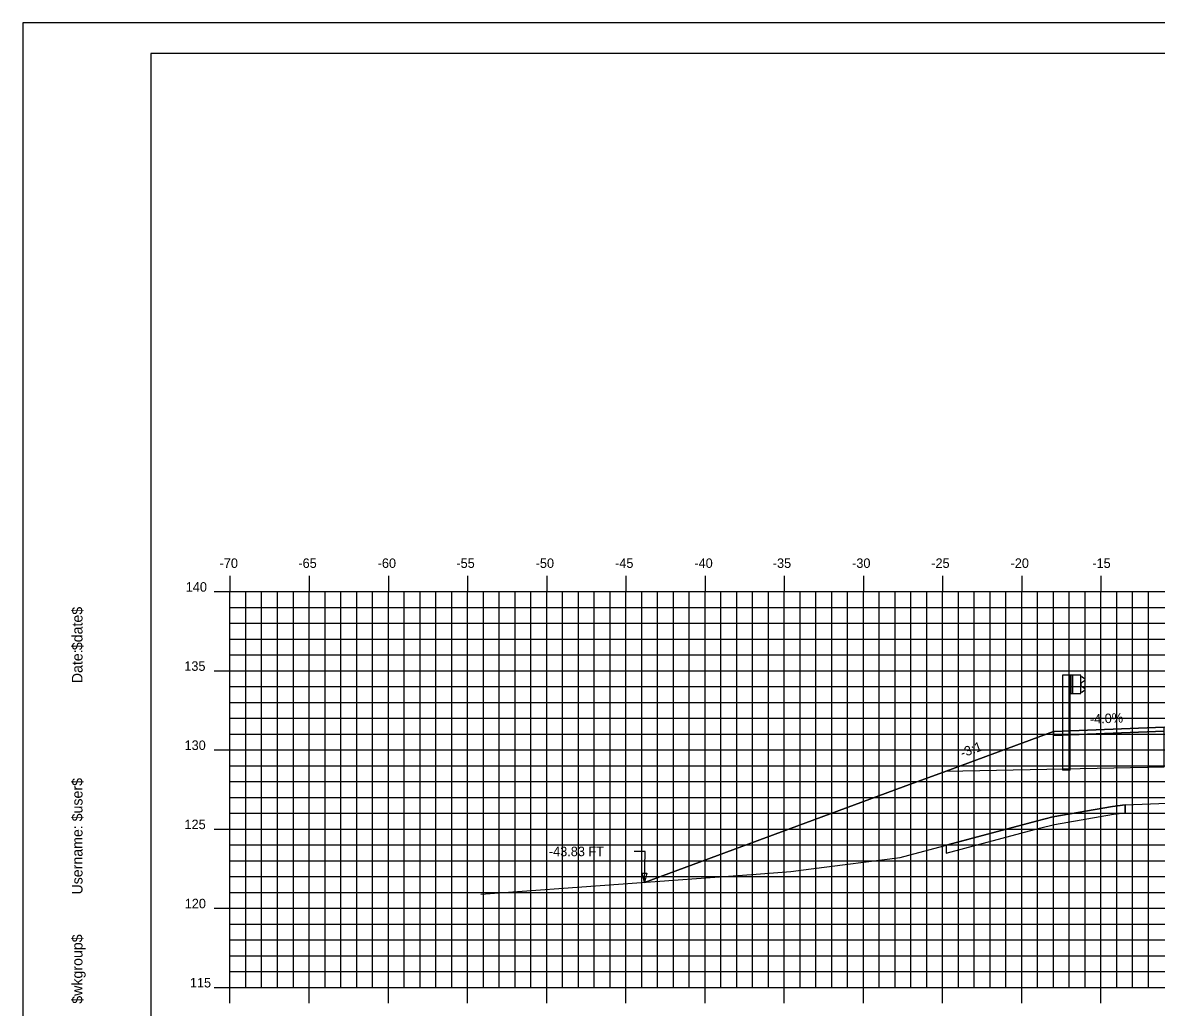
# Model space of a CAD drawing. Extents: x 1146081 to 1146251, y 608981 to 609091.
# Drawn here: x 1146081.1 to 1146152.7, y 609029.1 to 609091.3 of the extents above; entities that cross this region are included whole.
import ezdxf

# ---------------------------------------------------------------- set-up
doc = ezdxf.new("R2010")
doc.units = 0
for name, color, linetype in [('ANNOTATION', 7, 'Continuous'), ('BORDER', 7, 'Continuous'), ('D_Guardrail_Beam_Lt', 7, 'Continuous'), ('D_Roadway_Edge_Shoulder', 7, 'Continuous'), ('D_Roadway_SlopeLines', 7, 'Continuous'), ('D_Roadway_SubGrade', 7, 'Continuous'), ('D_Text_Standard', 7, 'Continuous'), ('H_V ANNOTATION', 7, 'Continuous'), ('MAJOR', 7, 'Continuous'), ('MINOR', 7, 'Continuous'), ('PLOT BOUNDARY', 7, 'Continuous'), ('S_Roadway_Centerline', 7, 'Continuous'), ('SHADING', 7, 'Continuous')]:
    doc.layers.add(name, color=color, linetype=linetype)

msp = doc.modelspace()

# ---------------------------------------------------------------- linework, layer by layer
msp.add_lwpolyline([(1146120.332, 609036.972), (1146136.678, 609043), (1146139.39, 609044), (1146146.157, 609046.495), (1146146.158, 609046.495), (1146153.158, 609046.775), (1146164.158, 609046.995), (1146175.158, 609046.775), (1146185.834, 609046.348), (1146193.131, 609043.915), (1146196.131, 609042.915), (1146201.256, 609041.207)])
at = {"layer": 'BORDER'}
msp.add_lwpolyline([(1146089.158, 608984.335), (1146249.158, 608984.335), (1146249.158, 609089.335), (1146089.158, 609089.335)], close=True, dxfattribs=at)
at = {"layer": 'D_Guardrail_Beam_Lt'}
for p, q in [((1146146.728, 609050.059), (1146146.728, 609044.059)), ((1146147.199, 609050.059), (1146146.728, 609050.059)), ((1146147.887, 609050.059), (1146147.199, 609050.059)), ((1146147.199, 609050.059), (1146147.199, 609048.892)), ((1146147.262, 609050.059), (1146147.262, 609048.892)), ((1146147.366, 609050.059), (1146147.366, 609048.892)), ((1146147.887, 609048.892), (1146147.887, 609050.059)), ((1146147.887, 609049.976), (1146147.961, 609049.961)), ((1146147.891, 609049.511), (1146147.891, 609049.44)), ((1146148.12, 609049.711), (1146147.925, 609049.575)), ((1146147.925, 609049.376), (1146148.12, 609049.24)), ((1146147.977, 609049.954), (1146148.12, 609049.854)), ((1146147.199, 609048.892), (1146147.887, 609048.892)), ((1146147.22, 609044.059), (1146147.22, 609048.892)), ((1146147.961, 609048.99), (1146147.887, 609048.976)), ((1146148.12, 609049.097), (1146147.977, 609048.997)), ((1146147.22, 609044.059), (1146146.728, 609044.059))]:
    msp.add_line(p, q, dxfattribs=at)
for centre, major_axis, start_param, end_param in [((1146147.97, 609049.511), (-0.0789, 0), 5.323254, 6.283185), ((1146147.97, 609049.44), (-0.0789, 0), 6.283185, 7.243116), ((1146147.953, 609049.92), (0.0417, 0), 0.959931, 1.376053), ((1146148.07, 609049.783), (0.0877, 0), 5.323254, 7.243116), ((1146147.953, 609049.031), (0.0417, 0), 4.907132, 5.323254), ((1146148.07, 609049.168), (0.0877, 0), 5.323254, 7.243116)]:
    msp.add_ellipse(centre, major_axis=major_axis, ratio=0.995501, start_param=start_param, end_param=end_param, dxfattribs=at)
at = {"layer": 'D_Roadway_Edge_Shoulder'}
msp.add_lwpolyline([(1146153.158, 609046.775), (1146146.158, 609046.495), (1146146.158, 609046.245), (1146153.158, 609046.525)], close=True, dxfattribs=at)
at = {"layer": 'D_Roadway_SlopeLines'}
for points in [[(1146139.39, 609044), (1146136.678, 609043)], [(1146136.678, 609043), (1146120.332, 609036.972)]]:
    msp.add_lwpolyline(points, dxfattribs=at)
at = {"layer": 'D_Roadway_SubGrade'}
for p, q in [((1146150.681, 609041.862), (1146150.681, 609041.362)), ((1146139.39, 609039.329), (1146139.39, 609038.812))]:
    msp.add_line(p, q, dxfattribs=at)
msp.add_lwpolyline([(1146153.158, 609046.358), (1146153.158, 609046.525), (1146146.158, 609046.245), (1146146.158, 609046.495), (1146146.157, 609046.495), (1146139.39, 609044), (1146153.158, 609044.275)], close=True, dxfattribs=at)
msp.add_lwpolyline([(1146139.39, 609038.812), (1146145.288, 609040.387), (1146146.223, 609040.633), (1146149.952, 609041.275), (1146150.681, 609041.359)], dxfattribs=at)
at = {"layer": 'D_Text_Standard'}
msp.add_lwpolyline([(1146120.332, 609036.972), (1146120.367, 609038.927), (1146119.687, 609038.927)], dxfattribs=at)
msp.add_lwpolyline([(1146120.332, 609036.972), (1146120.197, 609037.557), (1146120.488, 609037.552)], close=True, dxfattribs=at)
at = {"layer": 'MAJOR'}
for p, q in [((1146094.158, 609056.337), (1146094.158, 609055.335)), ((1146099.158, 609056.337), (1146099.158, 609055.335)), ((1146104.158, 609056.337), (1146104.158, 609055.335)), ((1146109.158, 609056.337), (1146109.158, 609055.335)), ((1146114.158, 609056.337), (1146114.158, 609055.335)), ((1146119.158, 609056.337), (1146119.158, 609055.335)), ((1146124.158, 609056.337), (1146124.158, 609055.335)), ((1146129.158, 609056.337), (1146129.158, 609055.335)), ((1146134.158, 609056.337), (1146134.158, 609055.335)), ((1146139.158, 609056.337), (1146139.158, 609055.335)), ((1146144.158, 609056.337), (1146144.158, 609055.335)), ((1146149.158, 609056.337), (1146149.158, 609055.335)), ((1146093.156, 609055.335), (1146094.158, 609055.335)), ((1146094.158, 609055.335), (1146234.158, 609055.335)), ((1146094.158, 609030.335), (1146094.158, 609055.335)), ((1146094.158, 609030.335), (1146094.158, 609055.335)), ((1146094.158, 609055.335), (1146234.158, 609055.335)), ((1146099.158, 609030.335), (1146099.158, 609055.335)), ((1146104.158, 609030.335), (1146104.158, 609055.335)), ((1146109.158, 609030.335), (1146109.158, 609055.335)), ((1146114.158, 609030.335), (1146114.158, 609055.335)), ((1146119.158, 609030.335), (1146119.158, 609055.335)), ((1146124.158, 609030.335), (1146124.158, 609055.335)), ((1146129.158, 609030.335), (1146129.158, 609055.335)), ((1146134.158, 609030.335), (1146134.158, 609055.335)), ((1146139.158, 609030.335), (1146139.158, 609055.335)), ((1146144.158, 609030.335), (1146144.158, 609055.335)), ((1146149.158, 609030.335), (1146149.158, 609055.335)), ((1146093.156, 609050.335), (1146094.158, 609050.335)), ((1146094.158, 609050.335), (1146234.158, 609050.335)), ((1146093.156, 609045.335), (1146094.158, 609045.335)), ((1146094.158, 609045.335), (1146234.158, 609045.335)), ((1146093.156, 609040.335), (1146094.158, 609040.335)), ((1146094.158, 609040.335), (1146234.158, 609040.335)), ((1146093.156, 609035.335), (1146094.158, 609035.335)), ((1146094.158, 609035.335), (1146234.158, 609035.335)), ((1146093.156, 609030.335), (1146094.158, 609030.335)), ((1146094.158, 609030.335), (1146234.158, 609030.335)), ((1146094.158, 609030.335), (1146234.158, 609030.335)), ((1146094.158, 609029.333), (1146094.158, 609030.335)), ((1146099.158, 609029.333), (1146099.158, 609030.335)), ((1146104.158, 609029.333), (1146104.158, 609030.335)), ((1146109.158, 609029.333), (1146109.158, 609030.335)), ((1146114.158, 609029.333), (1146114.158, 609030.335)), ((1146119.158, 609029.333), (1146119.158, 609030.335)), ((1146124.158, 609029.333), (1146124.158, 609030.335)), ((1146129.158, 609029.333), (1146129.158, 609030.335)), ((1146134.158, 609029.333), (1146134.158, 609030.335)), ((1146139.158, 609029.333), (1146139.158, 609030.335)), ((1146144.158, 609029.333), (1146144.158, 609030.335)), ((1146149.158, 609029.333), (1146149.158, 609030.335))]:
    msp.add_line(p, q, dxfattribs=at)
at = {"layer": 'MINOR'}
for p, q in [((1146095.158, 609030.335), (1146095.158, 609055.335)), ((1146096.158, 609030.335), (1146096.158, 609055.335)), ((1146097.158, 609030.335), (1146097.158, 609055.335)), ((1146098.158, 609030.335), (1146098.158, 609055.335)), ((1146100.158, 609030.335), (1146100.158, 609055.335)), ((1146101.158, 609030.335), (1146101.158, 609055.335)), ((1146102.158, 609030.335), (1146102.158, 609055.335)), ((1146103.158, 609030.335), (1146103.158, 609055.335)), ((1146105.158, 609030.335), (1146105.158, 609055.335)), ((1146106.158, 609030.335), (1146106.158, 609055.335)), ((1146107.158, 609030.335), (1146107.158, 609055.335)), ((1146108.158, 609030.335), (1146108.158, 609055.335)), ((1146110.158, 609030.335), (1146110.158, 609055.335)), ((1146111.158, 609030.335), (1146111.158, 609055.335)), ((1146112.158, 609030.335), (1146112.158, 609055.335)), ((1146113.158, 609030.335), (1146113.158, 609055.335)), ((1146115.158, 609030.335), (1146115.158, 609055.335)), ((1146116.158, 609030.335), (1146116.158, 609055.335)), ((1146117.158, 609030.335), (1146117.158, 609055.335)), ((1146118.158, 609030.335), (1146118.158, 609055.335)), ((1146120.158, 609030.335), (1146120.158, 609055.335)), ((1146121.158, 609030.335), (1146121.158, 609055.335)), ((1146122.158, 609030.335), (1146122.158, 609055.335)), ((1146123.158, 609030.335), (1146123.158, 609055.335)), ((1146125.158, 609030.335), (1146125.158, 609055.335)), ((1146126.158, 609030.335), (1146126.158, 609055.335)), ((1146127.158, 609030.335), (1146127.158, 609055.335)), ((1146128.158, 609030.335), (1146128.158, 609055.335)), ((1146130.158, 609030.335), (1146130.158, 609055.335)), ((1146131.158, 609030.335), (1146131.158, 609055.335)), ((1146132.158, 609030.335), (1146132.158, 609055.335)), ((1146133.158, 609030.335), (1146133.158, 609055.335)), ((1146135.158, 609030.335), (1146135.158, 609055.335)), ((1146136.158, 609030.335), (1146136.158, 609055.335)), ((1146137.158, 609030.335), (1146137.158, 609055.335)), ((1146138.158, 609030.335), (1146138.158, 609055.335)), ((1146140.158, 609030.335), (1146140.158, 609055.335)), ((1146141.158, 609030.335), (1146141.158, 609055.335)), ((1146142.158, 609030.335), (1146142.158, 609055.335)), ((1146143.158, 609030.335), (1146143.158, 609055.335)), ((1146145.158, 609030.335), (1146145.158, 609055.335)), ((1146146.158, 609030.335), (1146146.158, 609055.335)), ((1146147.158, 609030.335), (1146147.158, 609055.335)), ((1146148.158, 609030.335), (1146148.158, 609055.335)), ((1146150.158, 609030.335), (1146150.158, 609055.335)), ((1146151.158, 609030.335), (1146151.158, 609055.335)), ((1146152.158, 609030.335), (1146152.158, 609055.335)), ((1146094.158, 609054.335), (1146234.158, 609054.335)), ((1146094.158, 609054.335), (1146095.16, 609054.335)), ((1146094.158, 609053.335), (1146234.158, 609053.335)), ((1146094.158, 609053.335), (1146095.16, 609053.335)), ((1146094.158, 609052.335), (1146234.158, 609052.335)), ((1146094.158, 609052.335), (1146095.16, 609052.335)), ((1146094.158, 609051.335), (1146234.158, 609051.335)), ((1146094.158, 609051.335), (1146095.16, 609051.335)), ((1146094.158, 609049.335), (1146234.158, 609049.335)), ((1146094.158, 609049.335), (1146095.16, 609049.335)), ((1146094.158, 609048.335), (1146234.158, 609048.335)), ((1146094.158, 609048.335), (1146095.16, 609048.335)), ((1146094.158, 609047.335), (1146234.158, 609047.335)), ((1146094.158, 609047.335), (1146095.16, 609047.335)), ((1146094.158, 609046.335), (1146234.158, 609046.335)), ((1146094.158, 609046.335), (1146095.16, 609046.335)), ((1146094.158, 609044.335), (1146234.158, 609044.335)), ((1146094.158, 609044.335), (1146095.16, 609044.335)), ((1146094.158, 609043.335), (1146234.158, 609043.335)), ((1146094.158, 609043.335), (1146095.16, 609043.335)), ((1146094.158, 609042.335), (1146234.158, 609042.335)), ((1146094.158, 609042.335), (1146095.16, 609042.335)), ((1146094.158, 609041.335), (1146234.158, 609041.335)), ((1146094.158, 609041.335), (1146095.16, 609041.335)), ((1146094.158, 609039.335), (1146234.158, 609039.335)), ((1146094.158, 609039.335), (1146095.16, 609039.335)), ((1146094.158, 609038.335), (1146234.158, 609038.335)), ((1146094.158, 609038.335), (1146095.16, 609038.335)), ((1146094.158, 609037.335), (1146234.158, 609037.335)), ((1146094.158, 609037.335), (1146095.16, 609037.335)), ((1146094.158, 609036.335), (1146234.158, 609036.335)), ((1146094.158, 609036.335), (1146095.16, 609036.335)), ((1146094.158, 609034.335), (1146234.158, 609034.335)), ((1146094.158, 609034.335), (1146095.16, 609034.335)), ((1146094.158, 609033.335), (1146234.158, 609033.335)), ((1146094.158, 609033.335), (1146095.16, 609033.335)), ((1146094.158, 609032.335), (1146234.158, 609032.335)), ((1146094.158, 609032.335), (1146095.16, 609032.335)), ((1146094.158, 609031.335), (1146234.158, 609031.335)), ((1146094.158, 609031.335), (1146095.16, 609031.335))]:
    msp.add_line(p, q, dxfattribs=at)
at = {"layer": 'PLOT BOUNDARY'}
msp.add_lwpolyline([(1146081.065, 608981.276), (1146251.065, 608981.276), (1146251.065, 609091.276), (1146081.065, 609091.276)], close=True, dxfattribs=at)
at = {"layer": 'S_Roadway_Centerline'}
msp.add_lwpolyline([(1146109.994, 609036.218), (1146127.386, 609037.487), (1146129.573, 609037.653), (1146130.865, 609037.83), (1146136.476, 609038.551), (1146145.16, 609040.869), (1146146.117, 609041.121), (1146149.881, 609041.769), (1146150.681, 609041.862), (1146159.752, 609042.222), (1146161.743, 609042.288), (1146170.756, 609042.071), (1146172.573, 609042.017), (1146176.099, 609041.605), (1146176.621, 609041.535), (1146178.817, 609040.219), (1146184.994, 609036.462), (1146186.117, 609036.191), (1146189.498, 609037.815), (1146190.601, 609039.556), (1146199.152, 609040.937), (1146222.375, 609043.92)], dxfattribs=at)
at = {"layer": 'SHADING'}
for p, q in [((1146150.681, 609041.362), (1146150.681, 609041.862)), ((1146139.39, 609039.329), (1146139.39, 609038.812))]:
    msp.add_line(p, q, dxfattribs=at)
for points in [[(1146150.681, 609041.862), (1146149.881, 609041.769), (1146146.117, 609041.121), (1146145.16, 609040.869), (1146139.39, 609039.329)], [(1146139.39, 609038.812), (1146145.288, 609040.387), (1146146.223, 609040.633), (1146149.952, 609041.275), (1146150.681, 609041.362)]]:
    msp.add_lwpolyline(points, dxfattribs=at)

# ---------------------------------------------------------------- texts
at = {"layer": 'ANNOTATION'}
for s, rotation, p in [('-4.0%', 2.29061, (1146148.474, 609046.988)), ('-3:1', 20.24053, (1146140.412, 609044.842))]:
    msp.add_text(s, height=0.6, rotation=rotation, dxfattribs=at).set_placement(p)
at = {"layer": 'BORDER'}
for s, p in [('$date$', (1146084.843, 609051.64)), ('Date:', (1146084.843, 609049.552)), ('$user$', (1146084.843, 609040.827)), ('Username:', (1146084.843, 609036.203)), ('$wkgroup$', (1146084.843, 609029.305))]:
    msp.add_text(s, height=0.6696, rotation=90, dxfattribs=at).set_placement(p)
at = {"layer": 'D_Text_Standard'}
msp.add_text('-43.83 FT', height=0.6, dxfattribs=at).set_placement((1146114.297, 609038.627))
at = {"layer": 'H_V ANNOTATION'}
for s, p in [('-70', (1146093.5, 609056.835)), ('-65', (1146098.476, 609056.835)), ('-60', (1146103.484, 609056.835)), ('-55', (1146108.454, 609056.835)), ('-50', (1146113.462, 609056.835)), ('-45', (1146118.476, 609056.835)), ('-40', (1146123.484, 609056.835)), ('-35', (1146128.438, 609056.835)), ('-30', (1146133.446, 609056.835)), ('-25', (1146138.444, 609056.835)), ('-20', (1146143.452, 609056.835)), ('-15', (1146148.615, 609056.835)), ('140', (1146091.363, 609055.335)), ('135', (1146091.272, 609050.335)), ('130', (1146091.288, 609045.335)), ('125', (1146091.283, 609040.335)), ('120', (1146091.299, 609035.335)), ('115', (1146091.625, 609030.335))]:
    msp.add_text(s, height=0.6, dxfattribs=at).set_placement(p)
at = {"layer": 'MAJOR'}
msp.add_text('-', height=0.006, dxfattribs=at).set_placement((1146094.154, 609030.335))

doc.saveas('drawing.dxf')
